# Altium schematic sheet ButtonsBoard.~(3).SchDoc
size A4
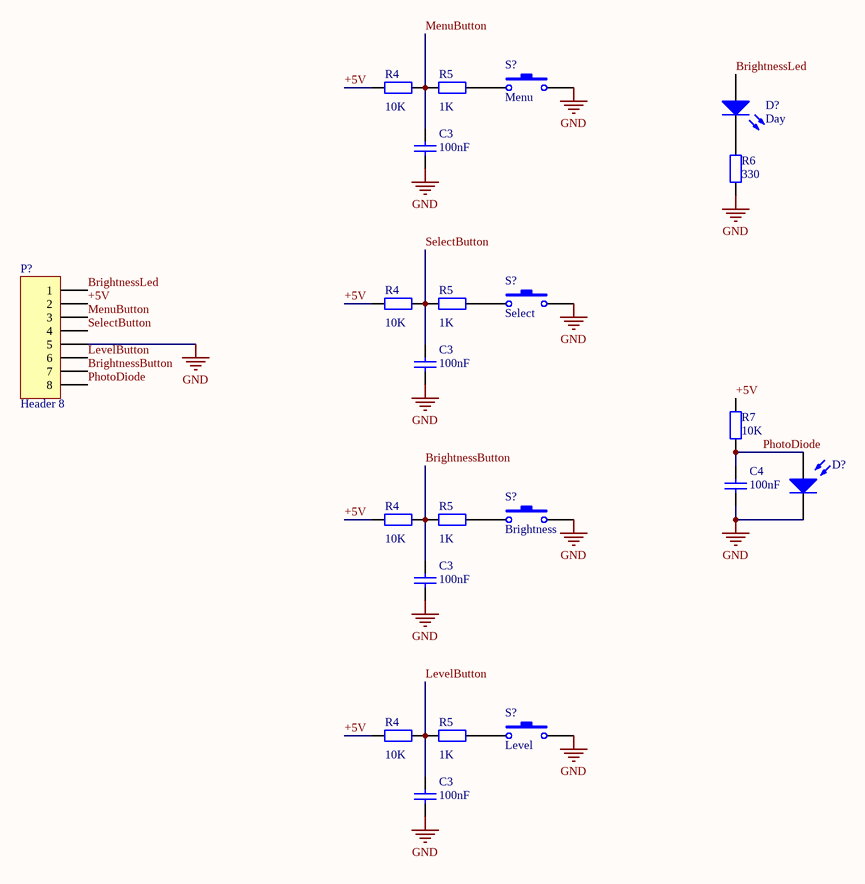
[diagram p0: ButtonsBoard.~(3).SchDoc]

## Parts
(Parts that share a designator on the sheet are numbered #1, #2 ... from top to bottom, then left to right.)
C3#1  value 100nF  [RAD-0.3]  (hidden comment: Cap)
C3#2  value 100nF  [RAD-0.3]  (hidden comment: Cap)
C3#3  value 100nF  [RAD-0.3]  (hidden comment: Cap)
C3#4  value 100nF  [RAD-0.3]  (hidden comment: Cap)
C4  value 100nF  [RAD-0.3]  (hidden comment: Cap)
D?#1  Day  [LED-0]
D?#2  Photo Sen  [PIN2]  (value not drawn)
P?  Header 8  [HDR1X8]
R4#1  value 10K  [AXIAL-0.4]  (hidden comment: Res2)
R4#2  value 10K  [AXIAL-0.4]  (hidden comment: Res2)
R4#3  value 10K  [AXIAL-0.4]  (hidden comment: Res2)
R4#4  value 10K  [AXIAL-0.4]  (hidden comment: Res2)
R5#1  value 1K  [AXIAL-0.4]  (hidden comment: Res2)
R5#2  value 1K  [AXIAL-0.4]  (hidden comment: Res2)
R5#3  value 1K  [AXIAL-0.4]  (hidden comment: Res2)
R5#4  value 1K  [AXIAL-0.4]  (hidden comment: Res2)
R6  value 330  [AXIAL-0.4]  (hidden comment: Res2)
R7  value 10K  [AXIAL-0.4]  (hidden comment: Res2)
S?#1  Menu  [SPST-2]
S?#2  Select  [SPST-2]
S?#3  Brightness  [SPST-2]
S?#4  Level  [SPST-2]

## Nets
GND: C3#1.1 C3#2.1 C3#3.1 C3#4.1 C4.1 D?#2.2(K) P?.5 R6.1 S?#1.2 S?#2.2 S?#3.2 S?#4.2
+5V: P?.2 R4#1.1 R4#2.1 R4#3.1 R4#4.1 R7.2
BrightnessButton: C3#3.2 P?.7 R4#3.2 R5#3.1
BrightnessLed: D?#1.1(A) P?.1
LevelButton: C3#4.2 P?.6 R4#4.2 R5#4.1
MenuButton: C3#1.2 P?.3 R4#1.2 R5#1.1
PhotoDiode: C4.2 D?#2.1(A) P?.8 R7.1
SelectButton: C3#2.2 P?.4 R4#2.2 R5#2.1
NetD?#1_2: D?#1.2(K) R6.2
NetR5#1_2: R5#1.2 S?#1.1
NetR5#2_2: R5#2.2 S?#2.1
NetR5#3_2: R5#3.2 S?#3.1
NetR5#4_2: R5#4.2 S?#4.1

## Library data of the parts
C3#1-C3#4 C4 = Cap: Capacitor
D?#1 = LED0: Typical INFRARED GaAs LED
D?#2 = Photo Sen: Photosensitive Diode
P? = Header 8: Header, 8-Pin
R4#1-R4#4 R5#1-R5#4 R6 R7 = Res2: Resistor
S?#1-S?#4 = SW-PB: Switch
